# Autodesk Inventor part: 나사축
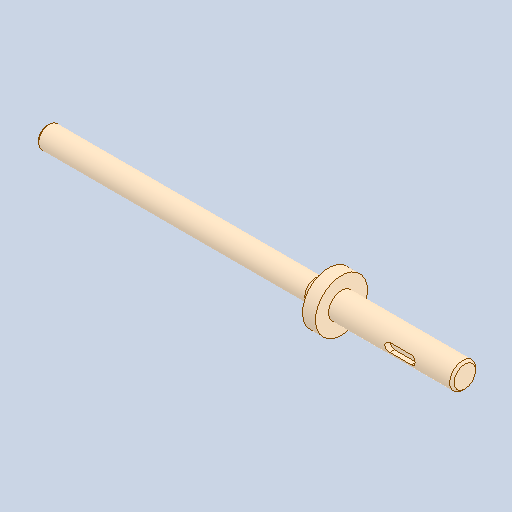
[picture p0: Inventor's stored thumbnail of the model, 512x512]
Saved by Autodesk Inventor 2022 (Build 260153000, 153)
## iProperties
Created: 2024-07
Part Number: 나사축
Material: 강철, 연강
Document SubType Name: Modeling
Designer: PC-01
Density: 7.86 g/cm^3
Appearance: 기본값
Author: jhkim
Sending System: Autodesk Inventor 2025
Preprocessor: ST-DEVELOPER v20
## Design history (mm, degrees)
feature "솔리드1"
node "솔리드2"
